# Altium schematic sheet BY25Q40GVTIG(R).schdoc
size 127 x 101 mm
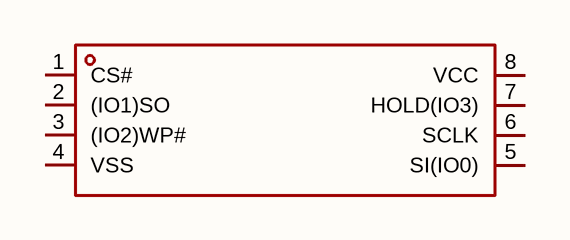
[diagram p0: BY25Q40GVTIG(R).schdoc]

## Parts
U?  by25q40gvtig(r)  [SOP-8_L4.9-W3.9-P1.27-LS6.0-BL]  (value not drawn)

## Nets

Not connected (* = marked no-connect by the designer): U? 1(CS#) 2((IO1)SO) 3((IO2)WP#) 4(VSS) 5(SI(IO0)) 6(SCLK) 7(HOLD(IO3)) 8(VCC)

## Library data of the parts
U? = by25q40gvtig(r): 接口类型:SPI;存储容量:4Mbit;时钟频率(fc):85MHz;; Manufacturer: BOYAMICRO(博雅); AddInBom: yes; ModelId: 75c24a7891ee4dd6bdac16a7163ff87e; ModelName: SOP-8_L4.9-W3.9-P1.27-LS6.0-BL-1; ModelTransform: 192.913,236.22,0,0,0,0,-0.393,2.749,0; Interface: SPI; Memory Size: 4Mbit; Clock Frequency: 85MHz; Voltage - Supply: 2.3V~3.6V; Standby Supply Current: 0.6uA; Program / Erase Cycles: 100000次; Page Programming Time (Tpp): 2ms; Block Erase Time(tBE): 8ms; Data Retention - TDR (Year): 20年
